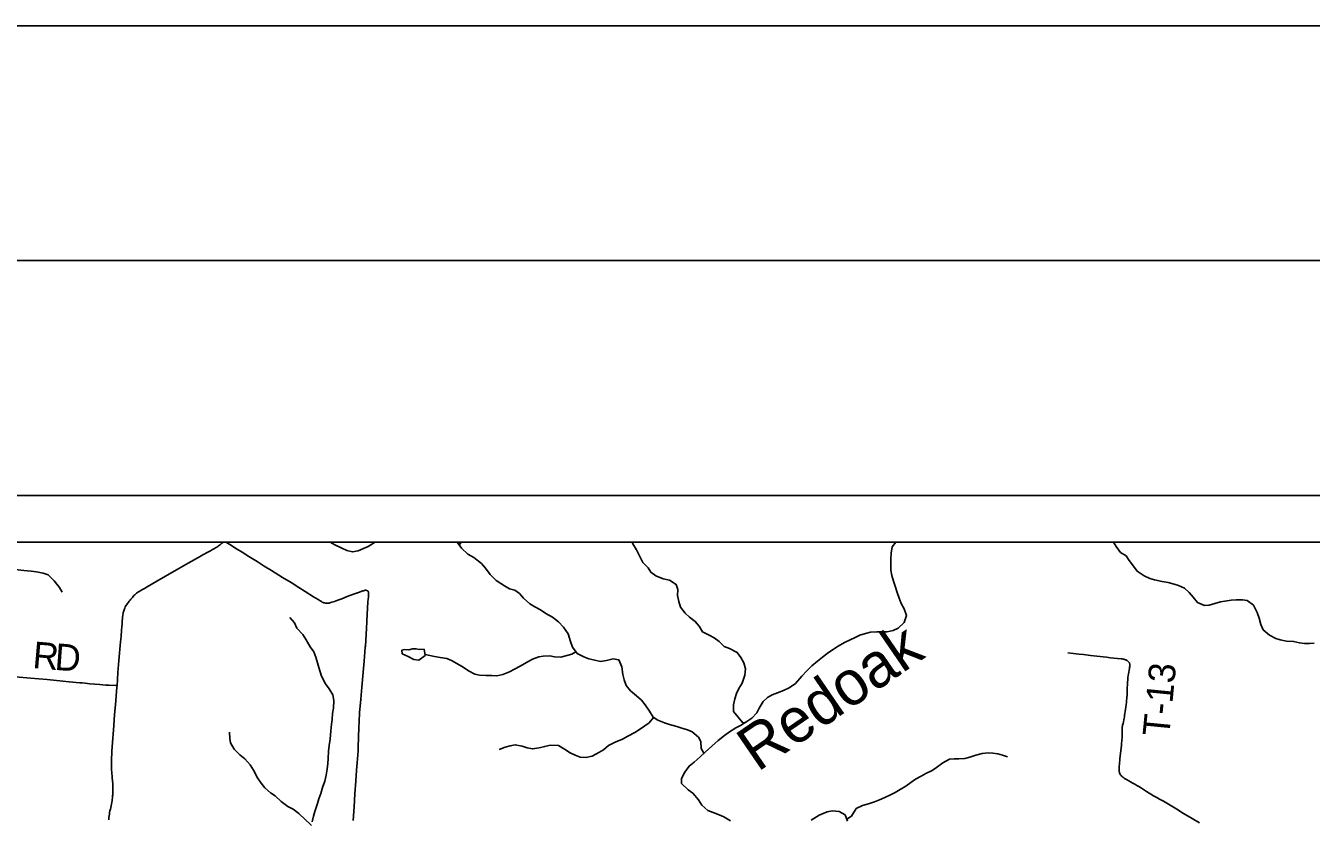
# Model space of a CAD drawing. Extents: x 0 to 34, y 0 to 22.
# Drawn here: x 4.632 to 7.37, y 20.31 to 22 of the extents above; entities that cross this region are included whole.
import ezdxf

# ---------------------------------------------------------------- set-up
doc = ezdxf.new("R2010")
doc.units = 0
for name, color, linetype in [('Default', 7, 'Continuous'), ('GM_X_County_Road', 7, 'Continuous'), ('GM_X_Minor_Lake', 7, 'Continuous'), ('GM_X_Minor_River', 7, 'Continuous'), ('GM_X_Minor_River_Text', 7, 'Continuous'), ('GM_X_Township_Road', 7, 'Continuous'), ('GM_X_Township_Road_Text', 7, 'Continuous'), ('SH_Border', 7, 'Continuous'), ('SH_Cut_Line', 7, 'Continuous'), ('SH_Data', 7, 'Continuous')]:
    doc.layers.add(name, color=color, linetype=linetype)

msp = doc.modelspace()

# ---------------------------------------------------------------- linework, layer by layer
at = {"layer": 'Default'}
msp.add_lwpolyline([(9.1142, 17.7402), (9.1142, 20.5497), (8.8095, 20.7701), (8.7304, 20.823), (8.6734, 20.858), (8.6167, 20.8996), (2.3571, 20.8996)], dxfattribs=at)
at = {"layer": 'GM_X_County_Road'}
for points in [[(4.8263, 20.5941), (4.8283, 20.6225), (4.8305, 20.6478), (4.8337, 20.6873), (4.8348, 20.699), (4.8359, 20.7123), (4.8365, 20.7193), (4.8371, 20.7256), (4.8376, 20.7312), (4.8381, 20.7386), (4.8388, 20.745), (4.8391, 20.7478), (4.8394, 20.7497), (4.8399, 20.7517), (4.8405, 20.7535), (4.8412, 20.7556), (4.8419, 20.7577), (4.843, 20.7596), (4.844, 20.7618), (4.8452, 20.7639), (4.8471, 20.7669), (4.8485, 20.769), (4.8505, 20.7718), (4.8522, 20.7741), (4.854, 20.7764), (4.8558, 20.7784), (4.8573, 20.7802), (4.859, 20.7821), (4.8605, 20.7838), (4.8624, 20.7859), (4.8644, 20.7878), (4.8663, 20.7895), (4.8681, 20.7911), (4.8701, 20.7926), (4.8722, 20.7941), (4.8746, 20.7957), (4.8768, 20.797), (4.8795, 20.7986), (4.8845, 20.8015), (4.8904, 20.805), (4.9108, 20.8167), (4.9529, 20.8406), (4.9779, 20.855), (5.0017, 20.8687), (5.0088, 20.8726), (5.0196, 20.8786), (5.0252, 20.8817), (5.0298, 20.8841), (5.0337, 20.8863), (5.0363, 20.8877), (5.0388, 20.8893), (5.0408, 20.8905), (5.0428, 20.8919), (5.0448, 20.8934), (5.0467, 20.8949), (5.0485, 20.8963), (5.0499, 20.8975), (5.0511, 20.8987), (5.0518, 20.8996)], [(4.8087, 20.3082), (4.8089, 20.311), (4.8092, 20.3137), (4.8095, 20.3166), (4.81, 20.3204), (4.8106, 20.324), (4.8113, 20.3275), (4.8121, 20.3312), (4.8128, 20.3344), (4.8135, 20.338), (4.8143, 20.3415), (4.8152, 20.346), (4.8157, 20.3488), (4.8161, 20.3515), (4.8165, 20.3543), (4.8168, 20.357), (4.817, 20.3594), (4.8171, 20.3619), (4.8173, 20.3649), (4.8175, 20.3688), (4.8175, 20.3727), (4.8176, 20.376), (4.8175, 20.3795), (4.8173, 20.3831), (4.8171, 20.3865), (4.8169, 20.3898), (4.8166, 20.3932), (4.8163, 20.3964), (4.816, 20.3999), (4.8157, 20.4026), (4.8154, 20.406), (4.8151, 20.4097), (4.8147, 20.4143), (4.8144, 20.4189), (4.8144, 20.4229), (4.8143, 20.4262), (4.8144, 20.4296), (4.8144, 20.4344), (4.8147, 20.4409), (4.8151, 20.4474), (4.8155, 20.4545), (4.8162, 20.4636), (4.8194, 20.5094), (4.8212, 20.533), (4.8228, 20.5532), (4.8261, 20.5908), (4.8263, 20.5941)]]:
    msp.add_lwpolyline(points, dxfattribs=at)
at = {"layer": 'GM_X_Minor_Lake'}
for points in [[(5.4805, 20.6716), (5.4706, 20.6709), (5.4631, 20.6729), (5.4555, 20.6723), (5.4479, 20.6705), (5.4388, 20.6714), (5.4331, 20.6699), (5.4338, 20.6623), (5.4462, 20.6561), (5.4582, 20.6499), (5.4692, 20.6482), (5.483, 20.6586)], [(5.483, 20.6586), (5.4805, 20.6716)]]:
    msp.add_lwpolyline(points, dxfattribs=at)
at = {"layer": 'GM_X_Minor_River'}
msp.add_line((5.5552, 20.8934), (5.5594, 20.8996), dxfattribs=at)
for points in [[(4.4696, 20.8996), (4.4752, 20.8931), (4.4928, 20.8736), (4.5062, 20.8609), (4.5164, 20.8562), (4.53, 20.8518), (4.5421, 20.849), (4.5523, 20.847), (4.5622, 20.8457), (4.5731, 20.8444), (4.586, 20.8435), (4.5978, 20.8422), (4.6095, 20.8413), (4.6281, 20.8395), (4.6436, 20.8378), (4.6546, 20.8365), (4.6689, 20.8337), (4.6799, 20.8301), (4.6926, 20.8174), (4.7038, 20.8036), (4.7094, 20.7937)], [(5.3751, 20.8996), (5.3723, 20.8978), (5.3612, 20.8904), (5.3513, 20.8867), (5.3402, 20.8812), (5.3281, 20.8791), (5.3156, 20.8823), (5.3035, 20.8881), (5.29, 20.894), (5.2803, 20.8996)], [(6.0765, 20.4503), (6.0704, 20.4604), (6.0698, 20.4752), (6.0647, 20.4847), (6.0515, 20.4955), (6.0414, 20.5002), (6.0293, 20.5038), (6.0187, 20.5073), (6.0028, 20.5117), (5.9923, 20.5153), (5.9783, 20.5204), (5.9681, 20.527), (5.9607, 20.5396), (5.951, 20.553), (5.9436, 20.563), (5.9331, 20.5726), (5.9199, 20.5834), (5.911, 20.5945), (5.9062, 20.6063), (5.9037, 20.6181), (5.9016, 20.634), (5.8954, 20.6489), (5.8829, 20.651), (5.8688, 20.6478), (5.8559, 20.646), (5.8438, 20.6485), (5.831, 20.6513), (5.8208, 20.6556), (5.8065, 20.663), (5.7964, 20.676), (5.792, 20.6882), (5.7869, 20.7046), (5.7772, 20.7191), (5.7664, 20.7299), (5.7536, 20.7403), (5.74, 20.7481), (5.728, 20.7558), (5.7163, 20.7624), (5.7058, 20.7682), (5.6923, 20.7806), (5.6837, 20.7905), (5.6736, 20.7975), (5.6622, 20.8007), (5.6513, 20.8065), (5.634, 20.8181), (5.6209, 20.8308), (5.6109, 20.8446), (5.6023, 20.8546), (5.5865, 20.8673), (5.5733, 20.8743), (5.5598, 20.8874), (5.5505, 20.8996)], [(6.1629, 20.5152), (6.1595, 20.5153), (6.149, 20.5268), (6.1393, 20.5395), (6.1391, 20.5535), (6.1423, 20.5663), (6.1455, 20.5773), (6.1509, 20.5878), (6.1579, 20.5995), (6.1638, 20.6165), (6.1647, 20.6301), (6.1611, 20.6431), (6.1552, 20.6545), (6.1473, 20.6649), (6.1307, 20.673), (6.1198, 20.6774), (6.1086, 20.6881), (6.0981, 20.6962), (6.0875, 20.7017), (6.0732, 20.7087), (6.0665, 20.7209), (6.0579, 20.7309), (6.0459, 20.7398), (6.0362, 20.7486), (6.0265, 20.7613), (6.0228, 20.7734), (6.02, 20.786), (6.0205, 20.7989), (6.0172, 20.8095), (6.0033, 20.8192), (5.9893, 20.8217), (5.9742, 20.8283), (5.9633, 20.8357), (5.9578, 20.8452), (5.9465, 20.8567), (5.9395, 20.8709), (5.9329, 20.8835), (5.9251, 20.8965), (5.9236, 20.8996)], [(6.4853, 20.8996), (6.477, 20.8898), (6.4749, 20.8761), (6.4748, 20.8636), (6.4743, 20.853), (6.4748, 20.8401), (6.4766, 20.8291), (6.4802, 20.8169), (6.4839, 20.8063), (6.4879, 20.7929), (6.4923, 20.7804), (6.4967, 20.7689), (6.5026, 20.7582), (6.5077, 20.7438), (6.503, 20.7287), (6.49, 20.7167), (6.4793, 20.7115), (6.4667, 20.7091), (6.4538, 20.7089), (6.4444, 20.709), (6.4315, 20.708), (6.4208, 20.7055), (6.4083, 20.7019), (6.3987, 20.6971), (6.388, 20.6915), (6.3758, 20.686), (6.3625, 20.6786), (6.3418, 20.6645), (6.3288, 20.6552), (6.3181, 20.6466), (6.3062, 20.6362), (6.2958, 20.6257), (6.2851, 20.6145), (6.2712, 20.5991), (6.2578, 20.5894), (6.246, 20.5839), (6.2331, 20.5791), (6.222, 20.5747), (6.2121, 20.5692), (6.2025, 20.5606), (6.1943, 20.5463), (6.1889, 20.5361), (6.1785, 20.5253), (6.1675, 20.5182), (6.1541, 20.5093), (6.1441, 20.5041), (6.1308, 20.4956), (6.1201, 20.4878), (6.107, 20.4773), (6.0936, 20.465), (6.079, 20.4527), (6.0687, 20.4426), (6.0553, 20.4314), (6.0449, 20.4228), (6.036, 20.4097), (6.0287, 20.3961), (6.0289, 20.3859), (6.0428, 20.372)], [(6.9491, 20.8996), (6.9543, 20.8905), (6.964, 20.8775), (6.9761, 20.8705), (6.9824, 20.8609), (6.9895, 20.8514), (6.9995, 20.838), (7.0142, 20.8283), (7.0263, 20.8228), (7.0364, 20.8193), (7.0523, 20.816), (7.0652, 20.8136), (7.0777, 20.8107), (7.0875, 20.8076), (7.0999, 20.8017), (7.11, 20.7929), (7.1182, 20.7825), (7.1276, 20.7714), (7.1423, 20.7651), (7.1529, 20.7657), (7.1647, 20.769), (7.1765, 20.7726), (7.186, 20.7744), (7.1997, 20.7761), (7.2103, 20.7771), (7.2232, 20.7773), (7.2334, 20.7757), (7.2469, 20.766), (7.2547, 20.75), (7.2587, 20.7378), (7.2623, 20.7245), (7.2679, 20.7134), (7.2814, 20.7015), (7.2942, 20.6945), (7.304, 20.6917), (7.3176, 20.6892), (7.3324, 20.6883), (7.3449, 20.6854), (7.3555, 20.6842), (7.3661, 20.684), (7.3759, 20.685)], [(5.2785, 20.4665), (5.2802, 20.4805), (5.2819, 20.4979), (5.2828, 20.5119), (5.2845, 20.5221), (5.2854, 20.5346), (5.2871, 20.5464), (5.288, 20.5623), (5.2859, 20.5744), (5.2781, 20.5871), (5.2703, 20.5978), (5.2618, 20.6142), (5.2563, 20.6328), (5.253, 20.6431), (5.2498, 20.6549), (5.2454, 20.666), (5.2375, 20.6767), (5.2294, 20.692), (5.222, 20.7035), (5.2092, 20.7165), (5.2045, 20.7283), (5.1947, 20.7391)], [(5.8037, 20.6666), (5.7954, 20.6616), (5.7715, 20.6551), (5.7582, 20.6557), (5.748, 20.6577), (5.7343, 20.6571), (5.7248, 20.6558), (5.7115, 20.6503), (5.6985, 20.6432), (5.6852, 20.6358), (5.673, 20.6295), (5.6623, 20.624), (5.6478, 20.6181), (5.6356, 20.6149), (5.625, 20.6158), (5.6121, 20.6159), (5.5981, 20.6169), (5.5883, 20.6189), (5.5751, 20.6259), (5.5634, 20.6337), (5.5499, 20.6414), (5.539, 20.648), (5.5288, 20.6523), (5.5148, 20.6544), (5.5027, 20.6561), (5.4827, 20.6603)], [(5.9691, 20.5263), (5.96, 20.5153), (5.9413, 20.5019), (5.9291, 20.4941), (5.9142, 20.4864), (5.9027, 20.4801), (5.8871, 20.4739), (5.873, 20.4665), (5.8622, 20.4575), (5.8527, 20.4519), (5.8382, 20.4438), (5.8249, 20.4409), (5.8128, 20.4419), (5.8022, 20.4462), (5.7916, 20.4513), (5.7792, 20.4586), (5.7664, 20.4668), (5.7486, 20.4674), (5.7372, 20.4649), (5.7254, 20.4616), (5.711, 20.4595), (5.6996, 20.4616), (5.6894, 20.4651), (5.6747, 20.4684), (5.6637, 20.4662), (5.653, 20.463), (5.6401, 20.4582)], [(5.2407, 20.2964), (5.2377, 20.299), (5.228, 20.3086), (5.2137, 20.3221), (5.2013, 20.3314), (5.1904, 20.3368), (5.1761, 20.3476), (5.163, 20.3592), (5.1532, 20.3658), (5.1412, 20.3765), (5.133, 20.3865), (5.1256, 20.398), (5.1171, 20.414), (5.11, 20.4255), (5.0984, 20.4385), (5.0879, 20.447), (5.0756, 20.4589), (5.0681, 20.4723), (5.0667, 20.4818), (5.0661, 20.4951)], [(5.2423, 20.3039), (5.2451, 20.3164), (5.2479, 20.3262), (5.253, 20.3432), (5.2562, 20.353), (5.2605, 20.3643), (5.2641, 20.3776), (5.2688, 20.3908), (5.2716, 20.4032), (5.2741, 20.4161), (5.275, 20.4282), (5.2759, 20.4388), (5.2768, 20.4544), (5.2785, 20.4665)], [(6.3806, 20.3099), (6.3909, 20.3165), (6.4009, 20.3323), (6.4143, 20.339), (6.4268, 20.3422), (6.4398, 20.347), (6.4504, 20.351), (6.4619, 20.3558), (6.4737, 20.3617), (6.4836, 20.3665), (6.4943, 20.3728), (6.5062, 20.3802), (6.5169, 20.388), (6.5268, 20.3951), (6.5394, 20.4017), (6.5493, 20.4069), (6.5623, 20.4135), (6.5719, 20.4199), (6.5856, 20.4295), (6.5998, 20.4373), (6.6096, 20.4383), (6.6195, 20.4382), (6.632, 20.4391), (6.6427, 20.442), (6.6556, 20.446), (6.6693, 20.45), (6.6815, 20.4514), (6.6917, 20.4505), (6.7027, 20.4488), (6.7125, 20.446), (6.7227, 20.4425)], [(6.0428, 20.372), (6.0529, 20.3655), (6.0652, 20.3509), (6.0719, 20.3394), (6.0847, 20.3282), (6.096, 20.3239), (6.1092, 20.3192), (6.119, 20.3149), (6.1329, 20.3064)], [(6.3051, 20.3078), (6.3219, 20.3182), (6.339, 20.3252), (6.3504, 20.3273), (6.3644, 20.3264), (6.3772, 20.319), (6.3824, 20.3053)]]:
    msp.add_lwpolyline(points, dxfattribs=at)
at = {"layer": 'GM_X_Township_Road'}
for points in [[(5.3551, 20.6762), (5.3553, 20.6782), (5.3575, 20.7159), (5.3589, 20.7466), (5.3595, 20.7583), (5.3606, 20.7734), (5.3611, 20.778), (5.3617, 20.7835), (5.3621, 20.7886), (5.3622, 20.7914), (5.3621, 20.7924), (5.362, 20.7933), (5.3617, 20.7941), (5.3613, 20.7948), (5.3609, 20.7954), (5.3601, 20.796), (5.3594, 20.7965), (5.3586, 20.7969), (5.3576, 20.7972), (5.3567, 20.7973), (5.3558, 20.7974), (5.3547, 20.7973), (5.3534, 20.797), (5.3516, 20.7965), (5.3496, 20.7959), (5.3404, 20.7927), (5.3301, 20.7889), (5.3163, 20.7839), (5.305, 20.7795), (5.2969, 20.7765), (5.2894, 20.7737), (5.2842, 20.7719), (5.2798, 20.7705), (5.2782, 20.7701), (5.2765, 20.7697), (5.275, 20.7696), (5.2737, 20.7696), (5.2726, 20.7696), (5.2716, 20.7697), (5.2703, 20.7699), (5.2683, 20.7704), (5.2669, 20.7708), (5.2651, 20.7715), (5.2636, 20.7723), (5.2617, 20.7733), (5.2589, 20.7749), (5.2545, 20.7776), (5.2447, 20.7836), (5.2274, 20.7947), (5.2139, 20.8031), (5.1969, 20.8136), (5.1787, 20.8249), (5.1553, 20.8395), (5.1399, 20.849), (5.1247, 20.8584), (5.107, 20.8696), (5.093, 20.8783), (5.0807, 20.886), (5.0668, 20.8948), (5.0634, 20.897), (5.0604, 20.8987), (5.0589, 20.8996)], [(5.3295, 20.3069), (5.3313, 20.3364), (5.333, 20.364), (5.3347, 20.3906), (5.3367, 20.4142), (5.3381, 20.4296), (5.3399, 20.4555), (5.3402, 20.4631), (5.3407, 20.4845), (5.3412, 20.5053), (5.3418, 20.5177), (5.3429, 20.5365), (5.3454, 20.5654), (5.3476, 20.5909), (5.3504, 20.6227), (5.3526, 20.6466), (5.3551, 20.6762)], [(6.8518, 20.6639), (6.8636, 20.6627), (6.8746, 20.6614), (6.8852, 20.6603), (6.8997, 20.6587), (6.9134, 20.6573), (6.9339, 20.6549), (6.9426, 20.6538), (6.9494, 20.653), (6.965, 20.6513), (6.9671, 20.651), (6.9691, 20.6507), (6.9706, 20.6504), (6.9719, 20.6502), (6.9729, 20.6499), (6.9744, 20.6494), (6.9753, 20.6491), (6.9763, 20.6486), (6.9774, 20.648), (6.9782, 20.6476), (6.9789, 20.6471), (6.9795, 20.6466), (6.9803, 20.6459), (6.981, 20.6452), (6.9816, 20.6445), (6.9822, 20.6436), (6.9826, 20.6428), (6.9831, 20.6417), (6.9834, 20.6406), (6.9836, 20.6393), (6.9836, 20.638), (6.9836, 20.6365), (6.9834, 20.6352), (6.9831, 20.6332), (6.9829, 20.6317)], [(6.9829, 20.6317), (6.9827, 20.6307), (6.9821, 20.6271), (6.9813, 20.6232), (6.9806, 20.6193), (6.98, 20.6154), (6.9795, 20.612), (6.979, 20.6067), (6.9785, 20.6018), (6.9783, 20.5969), (6.9781, 20.5896), (6.978, 20.5832), (6.9779, 20.5784), (6.9777, 20.574), (6.9774, 20.5692), (6.9771, 20.5659), (6.9766, 20.563), (6.9762, 20.5586), (6.9756, 20.5544), (6.9748, 20.5483), (6.9742, 20.5442), (6.9735, 20.5392), (6.9729, 20.535), (6.9725, 20.5314), (6.972, 20.528), (6.9716, 20.5249), (6.971, 20.5214), (6.9702, 20.5171), (6.9693, 20.5138), (6.9683, 20.5099), (6.9678, 20.5081), (6.9675, 20.5065), (6.9674, 20.5048), (6.9673, 20.5012), (6.9673, 20.4937), (6.9672, 20.4902), (6.9671, 20.4877), (6.9669, 20.4834), (6.9667, 20.4791), (6.9665, 20.476), (6.9661, 20.4717), (6.9656, 20.4673), (6.965, 20.4612), (6.9625, 20.4392), (6.9614, 20.4266), (6.961, 20.4231), (6.9609, 20.4207), (6.9607, 20.4185), (6.9606, 20.4166), (6.9606, 20.4152), (6.9607, 20.4136), (6.9609, 20.4116), (6.9613, 20.4099), (6.9619, 20.4082), (6.9626, 20.4067), (6.9632, 20.4054), (6.964, 20.4042), (6.965, 20.4028), (6.966, 20.4017), (6.967, 20.4006), (6.9679, 20.3998), (6.969, 20.399), (6.9706, 20.3978), (6.9725, 20.3966), (6.9766, 20.3942), (6.9812, 20.3916), (6.9852, 20.3893), (6.9886, 20.3873), (6.994, 20.3843), (6.9987, 20.3816), (7.0025, 20.3794), (7.0062, 20.3771), (7.0104, 20.3746), (7.0148, 20.3718), (7.0194, 20.3687), (7.0244, 20.3655), (7.0286, 20.3629), (7.0339, 20.3598), (7.0398, 20.3566), (7.0471, 20.3525), (7.0555, 20.3478), (7.0835, 20.3308), (7.0981, 20.3222), (7.1163, 20.3115), (7.1318, 20.3021)], [(4.6103, 20.6127), (4.642, 20.6102), (4.6601, 20.6085), (4.6778, 20.6071), (4.7111, 20.6039), (4.7245, 20.6026), (4.7473, 20.6005), (4.7518, 20.6001), (4.7588, 20.5994), (4.7686, 20.5984), (4.7898, 20.5965), (4.8027, 20.5955), (4.8094, 20.5951), (4.8238, 20.5942), (4.8263, 20.5941)]]:
    msp.add_lwpolyline(points, dxfattribs=at)
at = {"layer": 'SH_Border'}
msp.add_lwpolyline([(1.5, 21.5), (33.5, 21.5), (33.5, 0.5), (1.5, 0.5)], close=True, dxfattribs=at)
at = {"layer": 'SH_Cut_Line'}
msp.add_lwpolyline([(0, 0), (34, 0), (34, 22), (0, 22)], close=True, dxfattribs=at)
msp.add_lwpolyline([(9.1142, 14.0996), (9.1142, 20.8996), (2.3142, 20.8996)], dxfattribs=at)
at = {"layer": 'SH_Data'}
for p, q in [((2.2142, 20.9996), (9.2142, 20.9996)), ((2.3142, 20.8996), (9.1142, 20.8996))]:
    msp.add_line(p, q, dxfattribs=at)

# ---------------------------------------------------------------- texts
at = {"layer": 'GM_X_Minor_River_Text'}
msp.add_text('Redoak', height=0.09468, rotation=34.3904, dxfattribs=at).set_placement((6.1905, 20.4091))
at = {"layer": 'GM_X_Township_Road_Text'}
for s, height, rotation, p in [('R', 0.0568, 355.0722, (4.6451, 20.6319)), ('D', 0.0568, 355.7755, (4.6923, 20.6279)), ('T-13', 0.05682, 84.4278, (7.0672, 20.4843))]:
    msp.add_text(s, height=height, rotation=rotation, dxfattribs=at).set_placement(p)

doc.saveas('drawing.dxf')
